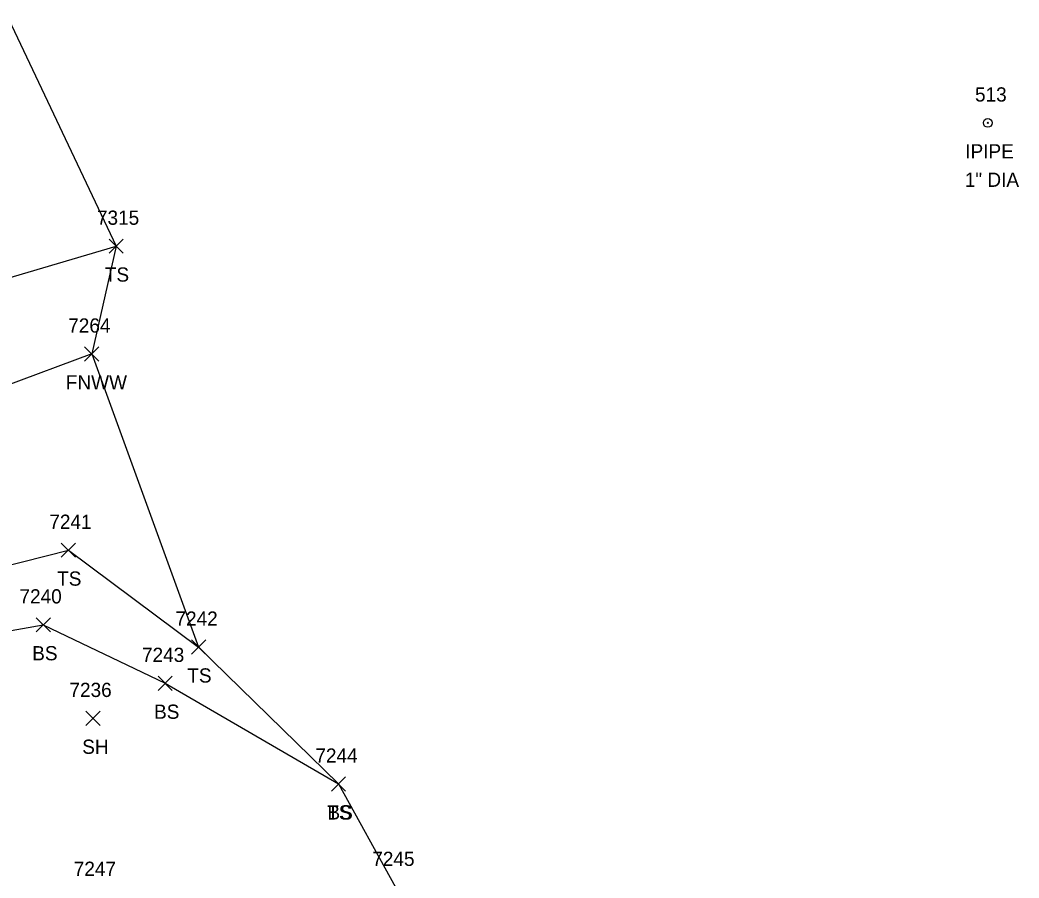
# Model space of a CAD drawing. Extents: x 1439173 to 1457902, y 641926 to 659889.
# Drawn here: x 1448744.2 to 1448884.8, y 644263.8 to 644384.5 of the extents above; entities that cross this region are included whole.
import ezdxf

# ---------------------------------------------------------------- set-up
doc = ezdxf.new("R2010")
doc.units = 0
for name, color, linetype in [('L_A', 7, 'Continuous'), ('L_I', 7, 'Continuous'), ('L_TIC', 7, 'Continuous'), ('LELB', 7, 'Continuous'), ('LFNC', 7, 'Continuous'), ('LSOGP', 7, 'Continuous'), ('M_A', 7, 'Continuous'), ('M_C', 7, 'Continuous'), ('M_I', 7, 'Continuous'), ('MPIP', 7, 'Continuous')]:
    doc.layers.add(name, color=color, linetype=linetype)

msp = doc.modelspace()

# ---------------------------------------------------------------- linework, layer by layer
at = {"layer": 'L_TIC'}
for points in [[(1448756.71, 644351.71), (1448758.71, 644353.71)], [(1448758.71, 644351.71), (1448756.71, 644353.71)], [(1448753.28, 644336.54), (1448755.28, 644338.54)], [(1448755.28, 644336.54), (1448753.28, 644338.54)], [(1448750, 644308.93), (1448752, 644310.93)], [(1448752, 644308.93), (1448750, 644310.93)], [(1448746.46, 644298.43), (1448748.46, 644300.43)], [(1448748.46, 644298.43), (1448746.46, 644300.43)], [(1448768.32, 644295.3), (1448770.32, 644297.3)], [(1448770.32, 644295.3), (1448768.32, 644297.3)], [(1448763.61, 644290.2), (1448765.61, 644292.2)], [(1448765.61, 644290.2), (1448763.61, 644292.2)], [(1448753.45, 644285.27), (1448755.45, 644287.27)], [(1448755.45, 644285.27), (1448753.45, 644287.27)], [(1448788.01, 644276.03), (1448790.01, 644278.03)], [(1448790.01, 644276.03), (1448788.01, 644278.03)], [(1448788.01, 644276.03), (1448790.01, 644278.03)], [(1448790.01, 644276.03), (1448788.01, 644278.03)]]:
    msp.add_lwpolyline(points, dxfattribs=at)
at = {"layer": 'LELB'}
for points in [[(1448835.67, 643920.01), (1448813.85, 643927.74), (1448807.25, 643938.49), (1448787.5, 643971.18), (1448769.8, 644005.91), (1448753.68, 644037.51), (1448732.59, 644075.62), (1448723.35, 644091.13), (1448721.47, 644097.94), (1448722.86, 644102.83), (1448722.46, 644106.41), (1448715.93, 644111.57), (1448711.76, 644124.49), (1448703.65, 644145.79), (1448694.94, 644171.31), (1448678.24, 644218.21), (1448664.75, 644266.64), (1448650.89, 644312.75), (1448655.72, 644319.77), (1448674.91, 644329.67), (1448705.26, 644337.73), (1448737.05, 644346.61), (1448757.71, 644352.71)], [(1448706.17, 644310.15), (1448727.82, 644295.93), (1448747.46, 644299.43), (1448764.61, 644291.2), (1448789.01, 644277.03)], [(1448706.17, 644310.15), (1448728.04, 644304.12), (1448751, 644309.93), (1448769.32, 644296.3), (1448789.01, 644277.03)]]:
    msp.add_lwpolyline(points, dxfattribs=at)
at = {"layer": 'LFNC'}
msp.add_lwpolyline([(1448754.28, 644337.54), (1448729.55, 644328.36), (1448709.25, 644325.15)], dxfattribs=at)
at = {"layer": 'LSOGP'}
msp.add_lwpolyline([(1448742.13, 644385.59), (1448757.71, 644352.71), (1448754.28, 644337.54), (1448769.32, 644296.29), (1448789.01, 644277.03), (1448797.02, 644262.5), (1448801.77, 644239.47), (1448814.21, 644216.5), (1448840.81, 644185.36), (1448858.37, 644140.81), (1448854.02, 644135.55), (1448849.75, 644118.15), (1448850.43, 644114.79), (1448850.19, 644107.52), (1448849.56, 644102.98), (1448856.91, 644066.77), (1448858.88, 644027.77)], dxfattribs=at)
at = {"layer": 'MPIP'}
for radius in [0.625, 0.0833]:
    msp.add_circle((1448880.39, 644370.05), radius, dxfattribs=at)

# ---------------------------------------------------------------- texts
at = {"layer": 'L_A'}
for s, p in [('TS', (1448756.12, 644347.71)), ('FNWW', (1448750.63, 644332.54)), ('TS', (1448749.41, 644304.93)), ('BS', (1448745.9, 644294.43)), ('TS', (1448767.73, 644291.3)), ('BS', (1448763.05, 644286.2)), ('SH', (1448752.94, 644281.27)), ('TS', (1448787.42, 644272.03)), ('BS', (1448787.45, 644272.03))]:
    msp.add_text(s, height=2, dxfattribs=at).set_placement(p)
at = {"layer": 'L_I'}
for s, p in [('7315', (1448755.01, 644355.71)), ('7264', (1448750.97, 644340.54)), ('7241', (1448748.31, 644312.93)), ('7240', (1448744.11, 644302.43)), ('7242', (1448766.06, 644299.3)), ('7243', (1448761.35, 644294.2)), ('7236', (1448751.14, 644289.27)), ('7244', (1448785.75, 644280.03)), ('7244', (1448785.75, 644280.03)), ('7245', (1448793.76, 644265.5)), ('7247', (1448751.75, 644264.1))]:
    msp.add_text(s, height=2, dxfattribs=at).set_placement(p)
at = {"layer": 'M_A'}
msp.add_text('IPIPE', height=2, dxfattribs=at).set_placement((1448877.22, 644365.05))
at = {"layer": 'M_C'}
msp.add_text('1" DIA', height=2, dxfattribs=at).set_placement((1448877.15, 644361.05))
at = {"layer": 'M_I'}
msp.add_text('513', height=2, dxfattribs=at).set_placement((1448878.59, 644373.05))

doc.saveas('drawing.dxf')
